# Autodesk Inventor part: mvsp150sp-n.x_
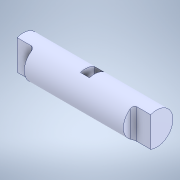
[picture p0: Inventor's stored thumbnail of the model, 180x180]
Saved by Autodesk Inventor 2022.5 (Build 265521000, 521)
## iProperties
Created: 2023-04
Part Number: mvsp150sp-n.x_
Material: Generic
Document SubType Name: Modeling
Designer: ImaoCorp
Density: 1 g/cm^3
Appearance: Default
Sending System: SOLIDWORKS 2021-2021301
MC: AMD64
MC_MODEL: Intel64 Family 6 Model 60 Stepping 3, GenuineIntel
OS: Windows_NT
FRU: Parasolid Version 32.1, build 255,  1- 1-2021
FORMAT: text
GUISE: transmit
KEY: mvsp150sp-n
FILE: mvsp150sp-n.x_t
DATE: Mon Apr 10 14:38:06 2023
Author: ImaoCorp
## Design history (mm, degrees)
feature "Base1"
node "ソリッド1"
